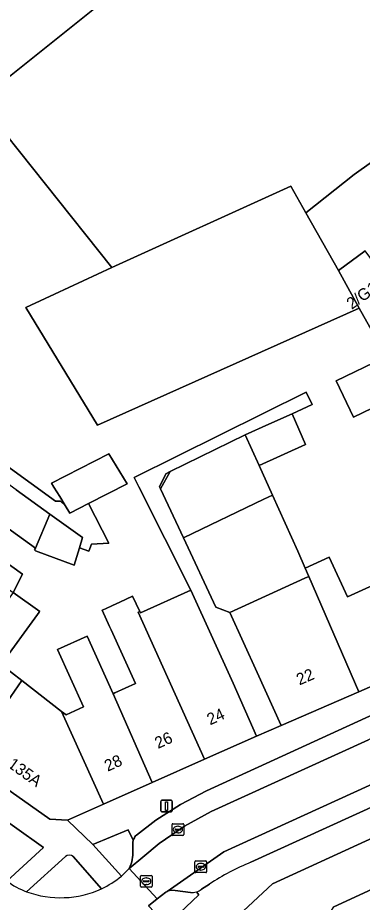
# Model space of a CAD drawing. Extents: x 159888 to 160761, y 384031 to 384750.
# Drawn here: x 160417.5 to 160447, y 384429.6 to 384505.5 of the extents above; entities that cross this region are included whole.
import ezdxf

# ---------------------------------------------------------------- set-up
doc = ezdxf.new("R2010")
doc.units = 0
for name, color, linetype in [('IMGEO_Erf', 7, 'Continuous'), ('IMGEO_Groenvoorziening', 7, 'Continuous'), ('IMGEO_Kolk', 7, 'Continuous'), ('IMGEO_Lichtmast', 7, 'Continuous'), ('IMGEO_Pand', 7, 'Continuous'), ('IMGEO_Pand_nummerreeks', 7, 'Continuous'), ('IMGEO_Parkeervlak_open', 7, 'Continuous'), ('IMGEO_Rijbaan_lokaal_open', 7, 'Continuous'), ('IMGEO_Rioolput', 7, 'Continuous'), ('IMGEO_Voetpad_open', 7, 'Continuous')]:
    doc.layers.add(name, color=color, linetype=linetype)

msp = doc.modelspace()

# ---------------------------------------------------------------- linework, layer by layer
at = {"layer": 'IMGEO_Erf'}
for points in [[(160416.215, 384500), (160420.926, 384503.774), (160424.352, 384506.518)], [(160447.939, 384478.504), (160446.781, 384480.59), (160424.315, 384470.545), (160418.182, 384480.642), (160425.564, 384484.062), (160414.155, 384498.367)], [(160416.253, 384458.924), (160417.898, 384457.746), (160417.099, 384456.165), (160419.365, 384454.543), (160419.316, 384454.476), (160419.174, 384454.282), (160416.049, 384450.003), (160417.841, 384448.611), (160421.24, 384445.97), (160421.626, 384445.67), (160423.124, 384446.364), (160420.901, 384451.268), (160423.435, 384452.417), (160425.67, 384447.488), (160425.819, 384447.556), (160427.589, 384448.358), (160425.504, 384452.959), (160425.363, 384453.269), (160424.736, 384454.653), (160425.008, 384454.779), (160425.619, 384455.063), (160426.249, 384455.355), (160427.34, 384455.861), (160427.953, 384454.538), (160428.008, 384454.421), (160432.325, 384456.378), (160427.882, 384465.235), (160427.475, 384466.047), (160442.228, 384473.375), (160442.751, 384472.322), (160441.011, 384471.52), (160442.173, 384468.89), (160438.192, 384467.061), (160439.333, 384464.529), (160441.499, 384459.722), (160442.136, 384458.255), (160444.209, 384459.216), (160445.767, 384455.789), (160450.11, 384457.763)], [(160416.537, 384467.042), (160420.722, 384464.026), (160421.159, 384464.026), (160421.546, 384463.637), (160421.081, 384464.403), (160420.593, 384465.207), (160420.382, 384465.554), (160425.303, 384468.069), (160426.867, 384465.493), (160423.553, 384463.8), (160425.294, 384460.421), (160423.82, 384460.321), (160423.581, 384459.716), (160422.784, 384460.003), (160422.334, 384458.513), (160419.002, 384459.761), (160418.91, 384459.834), (160419.014, 384459.979), (160413.505, 384463.928)], [(160454.815, 384428.715), (160452.913, 384432.978), (160451.074, 384432.172), (160448.254, 384430.872), (160444.591, 384429.182)]]:
    msp.add_lwpolyline(points, dxfattribs=at)
for points in [[(160444.786, 384474.343), (160448.835, 384476.282), (160450.329, 384473.162), (160446.28, 384471.223)], [(160430.565, 384466.552), (160430.189, 384466.367), (160429.648, 384465.256), (160429.729, 384465.084)], [(160441.499, 384459.722), (160439.333, 384464.529), (160438.958, 384464.349), (160438.593, 384464.173), (160431.702, 384460.857), (160434.478, 384454.91), (160435.664, 384454.454), (160442.116, 384457.4), (160442.443, 384457.55), (160442.136, 384458.255)]]:
    msp.add_lwpolyline(points, close=True, dxfattribs=at)
at = {"layer": 'IMGEO_Groenvoorziening'}
for points in [[(160413.255, 384436.472), (160411.98, 384434.883), (160412.745, 384434.274), (160414.458, 384432.998), (160415.329, 384432.331), (160415.468, 384432.225), (160416.553, 384431.409), (160419.706, 384434.291), (160414.703, 384437.839), (160413.518, 384436.561)], [(160427.346, 384434.651), (160427.348, 384434.674), (160427.359, 384434.768), (160427.379, 384434.86), (160427.397, 384434.917), (160426.956, 384435.794), (160423.935, 384434.536), (160426.374, 384431.834), (160427.031, 384432.494), (160427.125, 384432.697), (160427.202, 384432.874), (160427.263, 384433.057), (160427.308, 384433.245), (160427.335, 384433.436), (160427.346, 384433.628), (160427.346, 384433.645)]]:
    msp.add_lwpolyline(points, close=True, dxfattribs=at)
for points in [[(160421.576, 384433.512), (160418.245, 384430.493)], [(160424.664, 384430.743), (160422.239, 384433.502)], [(160430.292, 384430.519), (160430.182, 384430.443), (160429.448, 384429.895), (160428.687, 384429.27), (160430.268, 384427.625), (160433.005, 384430.213), (160432.805, 384430.473)], [(160432.316, 384430.415), (160431.001, 384430.598)]]:
    msp.add_lwpolyline(points, dxfattribs=at)
for centre, radius, start, end in [((160421.902, 384433.109), 0.518, 49.32173, 128.95003), ((160421.152, 384438.389), 8.414, 249.78985, 294.67088), ((160430.851, 384428.72), 1.884, 85.44161, 107.27425), ((160432.408, 384431.734), 1.322, 266.02865, 287.49978)]:
    msp.add_arc(centre, radius, start, end, dxfattribs=at)
at = {"layer": 'IMGEO_Kolk'}
for p, q in [((160430.721, 384435.404), (160430.721, 384436.256)), ((160430.796, 384436.33), (160431.648, 384436.33)), ((160430.98, 384435.824), (160430.98, 384435.836)), ((160431.418, 384435.787), (160431.02, 384435.787)), ((160431.023, 384435.873), (160431.421, 384435.873)), ((160431.209, 384436.11), (160431.234, 384436.11)), ((160431.464, 384435.836), (160431.464, 384435.824)), ((160431.722, 384436.256), (160431.722, 384435.404)), ((160431.648, 384435.33), (160430.796, 384435.33)), ((160431.232, 384435.55), (160431.207, 384435.55)), ((160432.688, 384432.205), (160432.688, 384433.057)), ((160432.763, 384433.131), (160433.615, 384433.131)), ((160432.947, 384432.625), (160432.947, 384432.637)), ((160433.385, 384432.588), (160432.987, 384432.588)), ((160432.99, 384432.674), (160433.388, 384432.674)), ((160433.176, 384432.911), (160433.201, 384432.911)), ((160433.431, 384432.637), (160433.431, 384432.625)), ((160433.689, 384433.057), (160433.689, 384432.205)), ((160433.615, 384432.131), (160432.763, 384432.131)), ((160433.199, 384432.351), (160433.174, 384432.351))]:
    msp.add_line(p, q, dxfattribs=at)
for points in [[(160430.721, 384435.404), (160430.721, 384436.256)], [(160430.796, 384436.33), (160431.648, 384436.33)], [(160431.722, 384436.256), (160431.722, 384435.404)], [(160431.648, 384435.33), (160430.796, 384435.33)], [(160432.688, 384432.205), (160432.688, 384433.057)], [(160432.763, 384433.131), (160433.615, 384433.131)], [(160433.689, 384433.057), (160433.689, 384432.205)], [(160433.615, 384432.131), (160432.763, 384432.131)]]:
    msp.add_lwpolyline(points, dxfattribs=at)
for centre, radius, start, end in [((160430.798, 384436.254), 0.0765, 91.55205, 178.44795), ((160430.798, 384436.254), 0.0765, 91.55205, 178.44795), ((160431.02, 384435.833), 0.0403, 85.87752, 175.75265), ((160431.017, 384435.823), 0.0366, 178.93798, 274.71019), ((160431.421, 384435.83), 0.043, 264.86636, 352.45326), ((160431.425, 384435.835), 0.0386, 1.73085, 96.63898), ((160431.646, 384436.254), 0.0765, 1.55205, 88.44795), ((160431.646, 384436.254), 0.0765, 1.55205, 88.44795), ((160430.798, 384435.406), 0.0765, 181.55205, 268.44795), ((160430.798, 384435.406), 0.0765, 181.55205, 268.44795), ((160431.646, 384435.406), 0.0765, 271.55205, 358.44795), ((160431.646, 384435.406), 0.0765, 271.55205, 358.44795), ((160432.765, 384433.055), 0.0765, 91.55205, 178.44795), ((160432.765, 384433.055), 0.0765, 91.55205, 178.44795), ((160432.987, 384432.634), 0.0403, 85.87752, 175.75265), ((160432.984, 384432.624), 0.0366, 178.93798, 274.71019), ((160433.388, 384432.631), 0.043, 264.86636, 352.45326), ((160433.392, 384432.636), 0.0386, 1.73085, 96.63898), ((160433.613, 384433.055), 0.0765, 1.55205, 88.44795), ((160433.613, 384433.055), 0.0765, 1.55205, 88.44795), ((160432.765, 384432.207), 0.0765, 181.55205, 268.44795), ((160432.765, 384432.207), 0.0765, 181.55205, 268.44795), ((160433.613, 384432.207), 0.0765, 271.55205, 358.44795), ((160433.613, 384432.207), 0.0765, 271.55205, 358.44795)]:
    msp.add_arc(centre, radius, start, end, dxfattribs=at)
for centre, major_axis, ratio, start_param, end_param in [((160431.208, 384435.83), (-0.387, 0.002), 0.722429, 4.712389, 7.853982), ((160431.233, 384435.83), (-0.39, 0.002), 0.717154, 1.570796, 4.712389), ((160433.175, 384432.631), (-0.387, 0.002), 0.722429, 4.712389, 7.853982), ((160433.2, 384432.631), (-0.39, 0.002), 0.717154, 1.570796, 4.712389)]:
    msp.add_ellipse(centre, major_axis=major_axis, ratio=ratio, start_param=start_param, end_param=end_param, dxfattribs=at)
at = {"layer": 'IMGEO_Lichtmast'}
for p, q in [((160429.749, 384437.443), (160429.749, 384438.243)), ((160429.749, 384438.243), (160429.749, 384437.443)), ((160429.849, 384438.343), (160430.639, 384438.343)), ((160430.639, 384438.343), (160429.849, 384438.343)), ((160430.739, 384438.243), (160430.739, 384437.443)), ((160430.739, 384437.443), (160430.739, 384438.243)), ((160430.639, 384437.343), (160429.849, 384437.343)), ((160429.849, 384437.343), (160430.639, 384437.343))]:
    msp.add_line(p, q, dxfattribs=at)
msp.add_lwpolyline([(160430.169, 384438.218), (160430.319, 384438.218), (160430.319, 384437.468), (160430.169, 384437.468), (160430.169, 384438.218)], dxfattribs=at)
for centre, start, end in [((160429.849, 384438.243), 90, 180), ((160429.849, 384438.243), 90, 180), ((160430.639, 384438.243), 0, 90), ((160430.639, 384438.243), 360, 90), ((160429.849, 384437.443), 180, 270), ((160429.849, 384437.443), 180, 270), ((160430.639, 384437.443), 270, 0), ((160430.639, 384437.443), 270, 0)]:
    msp.add_arc(centre, 0.1, start, end, dxfattribs=at)
at = {"layer": 'IMGEO_Pand'}
for points in [[(160488.936, 384534.93), (160487.757, 384536.875), (160482.889, 384544.99), (160479.793, 384550.133), (160479.161, 384549.765), (160471.203, 384543.477), (160445.899, 384523.596), (160424.352, 384506.518), (160420.926, 384503.774), (160416.215, 384500), (160414.155, 384498.367), (160425.564, 384484.062), (160440.9, 384491.039), (160442.203, 384488.75), (160446.354, 384492.06), (160454.254, 384497.681), (160453.942, 384498.111), (160454.092, 384498.231), (160452.683, 384500), (160449.739, 384503.694)], [(160425.564, 384484.062), (160418.182, 384480.642), (160424.315, 384470.545), (160446.781, 384480.59), (160444.994, 384483.809), (160442.203, 384488.75), (160440.9, 384491.039)], [(160444.994, 384483.809), (160446.781, 384480.59), (160447.939, 384478.504), (160450.897, 384480.609), (160447.299, 384485.504)], [(160444.786, 384474.343), (160446.28, 384471.223), (160450.329, 384473.162), (160448.835, 384476.282)], [(160441.011, 384471.52), (160439.022, 384470.627), (160437, 384469.708), (160438.192, 384467.061), (160442.173, 384468.89)], [(160438.192, 384467.061), (160437, 384469.708), (160430.565, 384466.552), (160429.729, 384465.084), (160431.702, 384460.857), (160438.593, 384464.173), (160438.958, 384464.349), (160439.333, 384464.529)], [(160420.382, 384465.554), (160420.593, 384465.207), (160421.081, 384464.403), (160421.546, 384463.637), (160421.946, 384462.979), (160423.553, 384463.8), (160426.867, 384465.493), (160425.303, 384468.069)], [(160417.346, 384464.98), (160415.23, 384466.496), (160413.505, 384463.928), (160419.014, 384459.979), (160420.24, 384462.906)], [(160423.052, 384460.892), (160420.24, 384462.906), (160419.014, 384459.979), (160418.91, 384459.834), (160419.002, 384459.761), (160422.334, 384458.513), (160422.784, 384460.003)], [(160450.11, 384457.763), (160445.767, 384455.789), (160444.209, 384459.216), (160442.136, 384458.255), (160442.443, 384457.55), (160446.743, 384447.659), (160453.303, 384450.51)], [(160415.075, 384457.615), (160417.099, 384456.165), (160417.898, 384457.746), (160416.253, 384458.924)], [(160442.443, 384457.55), (160442.116, 384457.4), (160435.664, 384454.454), (160438.01, 384449.315), (160440.087, 384444.766), (160446.743, 384447.659)], [(160416.049, 384450.003), (160419.174, 384454.282), (160419.316, 384454.476), (160419.365, 384454.543), (160417.099, 384456.165), (160408.862, 384444.715), (160413.074, 384441.752), (160417.841, 384448.611)], [(160432.325, 384456.378), (160428.008, 384454.421), (160427.953, 384454.538), (160427.809, 384454.473), (160433.515, 384441.874), (160437.974, 384443.854), (160435.95, 384448.381)], [(160427.809, 384454.473), (160427.953, 384454.538), (160427.34, 384455.861), (160426.249, 384455.355), (160425.619, 384455.063), (160425.008, 384454.779), (160424.736, 384454.653), (160425.363, 384453.269), (160425.504, 384452.959), (160427.589, 384448.358), (160425.819, 384447.556), (160425.67, 384447.488), (160429.014, 384439.875), (160433.515, 384441.874)], [(160425.67, 384447.488), (160423.435, 384452.417), (160420.901, 384451.268), (160423.124, 384446.364), (160421.626, 384445.67), (160421.24, 384445.97), (160424.848, 384438.013), (160429.014, 384439.875)], [(160421.24, 384445.97), (160417.841, 384448.611), (160413.074, 384441.752), (160420.223, 384436.724), (160421.761, 384436.633), (160424.848, 384438.013)], [(160442.489, 384427.081), (160442.579, 384427.165), (160444.334, 384428.795), (160444.591, 384429.182), (160448.254, 384430.872), (160451.074, 384432.172), (160452.913, 384432.978), (160454.815, 384428.715), (160457.405, 384430.008), (160455.56, 384434.139), (160453.93, 384437.792), (160447.309, 384434.839), (160439.345, 384431.166), (160433.504, 384425.741), (160433.519, 384424.249), (160436.258, 384421.313)]]:
    msp.add_lwpolyline(points, close=True, dxfattribs=at)
msp.add_lwpolyline([(160454.254, 384497.681), (160446.354, 384492.06), (160442.203, 384488.75), (160444.994, 384483.809), (160447.299, 384485.504)], dxfattribs=at)
at = {"layer": 'IMGEO_Parkeervlak_open'}
for points in [[(160518.317, 384471.834), (160497.824, 384462.524), (160495.213, 384461.332), (160455.807, 384443.337), (160453.206, 384442.149), (160435.156, 384433.906), (160430.297, 384430.523), (160430.292, 384430.519)], [(160450.082, 384446.662), (160433.681, 384439.158), (160431.447, 384437.988), (160429.327, 384436.622), (160427.659, 384435.344), (160427.595, 384435.275), (160427.537, 384435.2), (160427.486, 384435.121), (160427.443, 384435.037), (160427.407, 384434.95), (160427.397, 384434.917), (160427.379, 384434.86), (160427.359, 384434.768), (160427.348, 384434.674), (160427.346, 384434.651), (160427.346, 384433.645), (160427.346, 384433.628), (160427.335, 384433.436), (160427.308, 384433.245), (160427.263, 384433.057), (160427.202, 384432.874), (160427.125, 384432.697), (160427.031, 384432.494), (160428.207, 384433.465), (160429.629, 384434.635), (160431.79, 384436.112), (160434.074, 384437.389), (160447.578, 384443.534)], [(160437.486, 384433.018), (160452.963, 384440.089)], [(160433.237, 384430.708), (160433.925, 384431.14)], [(160431.001, 384430.598), (160432.316, 384430.415)]]:
    msp.add_lwpolyline(points, dxfattribs=at)
for centre, radius, start, end in [((160444.577, 384415.258), 19.123, 111.76406, 123.84847), ((160430.851, 384428.72), 1.884, 85.44161, 107.27425), ((160432.408, 384431.734), 1.322, 266.02865, 287.49978), ((160432.406, 384431.722), 1.311, 287.73572, 309.35502)]:
    msp.add_arc(centre, radius, start, end, dxfattribs=at)
at = {"layer": 'IMGEO_Rijbaan_lokaal_open'}
msp.add_lwpolyline([(160453.206, 384442.149), (160451.715, 384445.423), (160447.578, 384443.534), (160434.074, 384437.389), (160431.79, 384436.112), (160429.629, 384434.635), (160428.207, 384433.465), (160427.031, 384432.494), (160429.448, 384429.895), (160430.182, 384430.443), (160430.292, 384430.519), (160430.297, 384430.523), (160435.156, 384433.906)], close=True, dxfattribs=at)
msp.add_lwpolyline([(160428.687, 384429.27), (160429.448, 384429.895), (160427.031, 384432.494), (160426.374, 384431.834)], dxfattribs=at)
for centre, radius, start, end in [((160421.474, 384437.628), 7.588, 294.85752, 310.21918), ((160420.563, 384436.795), 6.714, 233.33266, 249.80767), ((160421.152, 384438.389), 8.414, 249.78985, 294.67088)]:
    msp.add_arc(centre, radius, start, end, dxfattribs=at)
at = {"layer": 'IMGEO_Rioolput'}
for p, q in [((160428.087, 384431.89), (160428.939, 384431.89)), ((160428.012, 384430.964), (160428.012, 384431.816)), ((160428.271, 384431.384), (160428.271, 384431.396)), ((160428.709, 384431.347), (160428.311, 384431.347)), ((160428.314, 384431.433), (160428.712, 384431.433)), ((160428.523, 384431.11), (160428.498, 384431.11)), ((160428.5, 384431.67), (160428.525, 384431.67)), ((160428.755, 384431.396), (160428.755, 384431.384)), ((160429.013, 384431.816), (160429.013, 384430.964)), ((160428.939, 384430.89), (160428.087, 384430.89))]:
    msp.add_line(p, q, dxfattribs=at)
for points in [[(160428.087, 384431.89), (160428.939, 384431.89)], [(160428.012, 384430.964), (160428.012, 384431.816)], [(160429.013, 384431.816), (160429.013, 384430.964)], [(160428.939, 384430.89), (160428.087, 384430.89)]]:
    msp.add_lwpolyline(points, dxfattribs=at)
for centre, radius, start, end in [((160428.089, 384431.814), 0.0765, 91.55205, 178.44795), ((160428.089, 384431.814), 0.0765, 91.55205, 178.44795), ((160428.937, 384431.814), 0.0765, 1.55205, 88.44795), ((160428.937, 384431.814), 0.0765, 1.55205, 88.44795), ((160428.311, 384431.393), 0.0403, 85.87752, 175.75265), ((160428.308, 384431.383), 0.0366, 178.93798, 274.71019), ((160428.712, 384431.39), 0.043, 264.86636, 352.45326), ((160428.716, 384431.395), 0.0386, 1.73085, 96.63898), ((160428.089, 384430.966), 0.0765, 181.55205, 268.44795), ((160428.089, 384430.966), 0.0765, 181.55205, 268.44795), ((160428.937, 384430.966), 0.0765, 271.55205, 358.44795), ((160428.937, 384430.966), 0.0765, 271.55205, 358.44795)]:
    msp.add_arc(centre, radius, start, end, dxfattribs=at)
for centre, major_axis, ratio, start_param, end_param in [((160428.499, 384431.39), (-0.387, 0.002), 0.722429, 4.712389, 7.853982), ((160428.524, 384431.39), (-0.39, 0.002), 0.717154, 1.570796, 4.712389)]:
    msp.add_ellipse(centre, major_axis=major_axis, ratio=ratio, start_param=start_param, end_param=end_param, dxfattribs=at)
at = {"layer": 'IMGEO_Voetpad_open'}
msp.add_lwpolyline([(160435.664, 384454.454), (160434.478, 384454.91), (160431.702, 384460.857), (160429.729, 384465.084), (160429.648, 384465.256), (160430.189, 384466.367), (160430.565, 384466.552), (160437, 384469.708), (160439.022, 384470.627), (160441.011, 384471.52), (160442.751, 384472.322), (160442.228, 384473.375), (160427.475, 384466.047), (160427.882, 384465.235), (160432.325, 384456.378), (160435.95, 384448.381), (160437.974, 384443.854), (160440.087, 384444.766), (160438.01, 384449.315)], close=True, dxfattribs=at)
for points in [[(160417.346, 384464.98), (160420.24, 384462.906), (160423.052, 384460.892), (160422.784, 384460.003), (160423.581, 384459.716), (160423.82, 384460.321), (160425.294, 384460.421), (160423.553, 384463.8), (160421.946, 384462.979), (160421.546, 384463.637), (160421.159, 384464.026), (160420.722, 384464.026), (160416.537, 384467.042)], [(160421.761, 384436.633), (160420.223, 384436.724), (160413.074, 384441.752), (160408.862, 384444.715), (160404.882, 384447.514), (160404.724, 384447.614), (160400.928, 384450.02), (160396.318, 384452.101), (160391.876, 384454.105), (160388.463, 384455.167), (160386.487, 384455.775), (160381.155, 384457.4), (160380.954, 384457.491), (160374.337, 384458.977), (160373.986, 384459.058), (160368.454, 384460.332), (160365.728, 384460.934)], [(160432.805, 384430.473), (160433.005, 384430.213), (160430.268, 384427.625), (160433.519, 384424.249), (160433.504, 384425.741), (160439.345, 384431.166), (160447.309, 384434.839), (160453.93, 384437.792), (160455.382, 384438.439), (160460.276, 384440.681), (160465.01, 384442.85), (160469.745, 384445.019), (160474.48, 384447.188), (160479.215, 384449.358), (160483.95, 384451.527)], [(160453.303, 384450.51), (160446.743, 384447.659), (160440.087, 384444.766), (160437.974, 384443.854), (160433.515, 384441.874), (160429.014, 384439.875), (160424.848, 384438.013), (160421.761, 384436.633), (160423.935, 384434.536), (160426.956, 384435.794), (160427.397, 384434.917), (160427.407, 384434.95), (160427.443, 384435.037), (160427.486, 384435.121), (160427.537, 384435.2), (160427.595, 384435.275), (160427.659, 384435.344), (160429.327, 384436.622), (160431.447, 384437.988), (160433.681, 384439.158), (160450.082, 384446.662)], [(160452.963, 384440.089), (160437.486, 384433.018)], [(160413.255, 384436.472), (160413.518, 384436.561), (160414.703, 384437.839), (160419.706, 384434.291), (160416.553, 384431.409)], [(160426.374, 384431.834), (160423.935, 384434.536), (160421.761, 384436.633)], [(160418.245, 384430.493), (160421.576, 384433.512)], [(160422.239, 384433.502), (160424.664, 384430.743)], [(160433.925, 384431.14), (160433.237, 384430.708)]]:
    msp.add_lwpolyline(points, dxfattribs=at)
for centre, radius, start, end in [((160421.902, 384433.109), 0.518, 49.32173, 128.95003), ((160444.577, 384415.258), 19.123, 111.76406, 123.84847), ((160421.474, 384437.628), 7.588, 294.85752, 310.21918), ((160420.563, 384436.795), 6.714, 233.33266, 249.80767), ((160432.406, 384431.722), 1.311, 287.73572, 309.35502)]:
    msp.add_arc(centre, radius, start, end, dxfattribs=at)

# ---------------------------------------------------------------- texts
at = {"layer": 'IMGEO_Pand_nummerreeks'}
for s, rotation, p in [('2/G11', 35.40843, (160446.132, 384480.432)), ('22', 23.49127, (160441.65, 384448.192)), ('24', 24.39081, (160433.988, 384444.768)), ('26', 24.37362, (160429.512, 384442.74)), ('135-135A', 324.18441, (160414.379, 384442.822)), ('28', 24.39081, (160425.194, 384440.781))]:
    msp.add_text(s, height=1, rotation=rotation, dxfattribs=at).set_placement(p)

doc.saveas('drawing.dxf')
